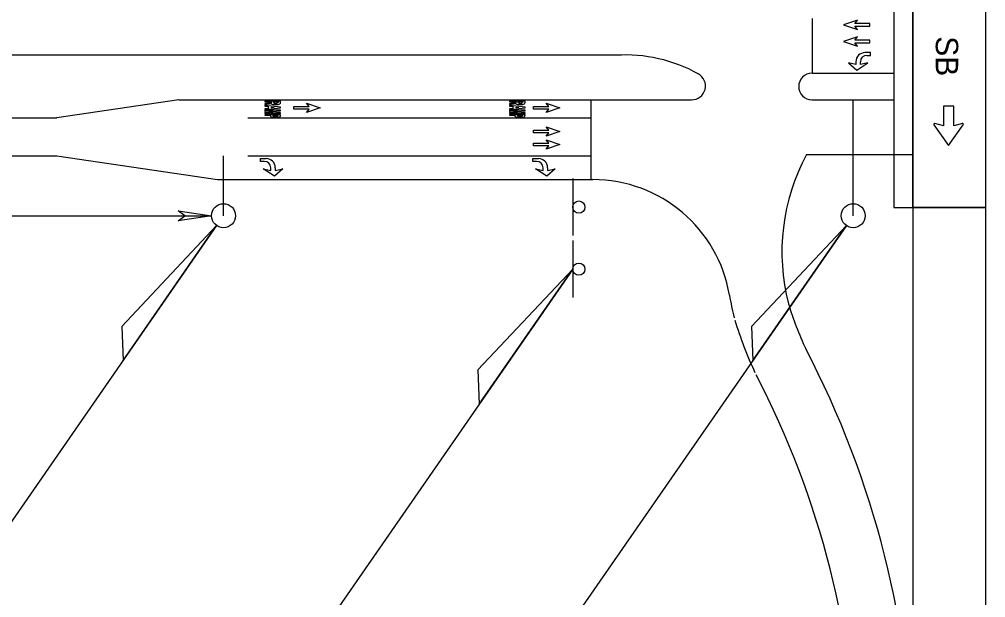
# Model space of a CAD drawing. Extents: x -830008.4 to -829992.7, y 1290284.1 to 1290294.4.
# Drawn here: x -830003.674 to -830000.185, y 1290287.925 to 1290290.014 of the extents above; entities that cross this region are included whole.
import ezdxf

# ---------------------------------------------------------------- set-up
doc = ezdxf.new("R2010")
doc.units = 0
for name, color, linetype in [('DirArrowsPavt', 7, 'Continuous'), ('LeaderLine_dp', 7, 'Continuous'), ('PavtMessage', 7, 'Continuous'), ('SignPanel', 7, 'Continuous'), ('SignSupport', 7, 'Continuous'), ('SignTruss', 7, 'Continuous'), ('TextLabel', 7, 'Continuous')]:
    doc.layers.add(name, color=color, linetype=linetype)

msp = doc.modelspace()

# ---------------------------------------------------------------- linework, layer by layer
at = {"layer": 'DirArrowsPavt'}
for p, q in [((-830000.6481, 1290290.0105), (-830000.6981, 1290289.9938)), ((-830000.6981, 1290289.9938), (-830000.6481, 1290289.9771)), ((-830000.6581, 1290289.9988), (-830000.6481, 1290290.0105)), ((-830000.6031, 1290289.9988), (-830000.6581, 1290289.9988)), ((-830000.6481, 1290289.9771), (-830000.6581, 1290289.9888)), ((-830000.6581, 1290289.9888), (-830000.6031, 1290289.9888)), ((-830000.6031, 1290289.9888), (-830000.6031, 1290289.9988)), ((-830000.6481, 1290289.9498), (-830000.6981, 1290289.9331)), ((-830000.6581, 1290289.9381), (-830000.6481, 1290289.9498)), ((-830000.6981, 1290289.9331), (-830000.6481, 1290289.9165)), ((-830000.6031, 1290289.9381), (-830000.6581, 1290289.9381)), ((-830000.6481, 1290289.9165), (-830000.6581, 1290289.9281)), ((-830000.6581, 1290289.9281), (-830000.6031, 1290289.9281)), ((-830000.6031, 1290289.9281), (-830000.6031, 1290289.9381)), ((-830000.6143, 1290289.8834), (-830000.6006, 1290289.8834)), ((-830002.6279, 1290289.6992), (-830002.6379, 1290289.7108)), ((-830002.6379, 1290289.7108), (-830002.5879, 1290289.6942)), ((-830001.7627, 1290289.6992), (-830001.7727, 1290289.7108)), ((-830001.7727, 1290289.7108), (-830001.7227, 1290289.6942)), ((-830002.6829, 1290289.6892), (-830002.6829, 1290289.6992)), ((-830002.6829, 1290289.6992), (-830002.6279, 1290289.6992)), ((-830002.6279, 1290289.6892), (-830002.6829, 1290289.6892)), ((-830002.5879, 1290289.6942), (-830002.6379, 1290289.6775)), ((-830002.6379, 1290289.6775), (-830002.6279, 1290289.6892)), ((-830001.8177, 1290289.6892), (-830001.8177, 1290289.6992)), ((-830001.8177, 1290289.6992), (-830001.7627, 1290289.6992)), ((-830001.7627, 1290289.6892), (-830001.8177, 1290289.6892)), ((-830001.7227, 1290289.6942), (-830001.7727, 1290289.6775)), ((-830001.7727, 1290289.6775), (-830001.7627, 1290289.6892)), ((-830001.8177, 1290289.6035), (-830001.8177, 1290289.6135)), ((-830001.8177, 1290289.6135), (-830001.7627, 1290289.6135)), ((-830001.7627, 1290289.6035), (-830001.8177, 1290289.6035)), ((-830001.7627, 1290289.6135), (-830001.7727, 1290289.6252)), ((-830001.7727, 1290289.6252), (-830001.7227, 1290289.6085)), ((-830001.7227, 1290289.6085), (-830001.7727, 1290289.5918)), ((-830001.7727, 1290289.5918), (-830001.7627, 1290289.6035)), ((-830001.8177, 1290289.5569), (-830001.8177, 1290289.5669)), ((-830001.8177, 1290289.5669), (-830001.7627, 1290289.5669)), ((-830001.7627, 1290289.5669), (-830001.7727, 1290289.5786)), ((-830001.7727, 1290289.5786), (-830001.7227, 1290289.5619)), ((-830001.7627, 1290289.5569), (-830001.8177, 1290289.5569)), ((-830001.7227, 1290289.5619), (-830001.7727, 1290289.5453)), ((-830001.7727, 1290289.5453), (-830001.7627, 1290289.5569)), ((-830002.7898, 1290289.5005), (-830002.8035, 1290289.5005)), ((-830001.8065, 1290289.5005), (-830001.8202, 1290289.5005))]:
    msp.add_line(p, q, dxfattribs=at)
for points in [[(-830000.6006, 1290289.8834), (-830000.6006, 1290289.8934), (-830000.6211, 1290289.8934)], [(-830000.6539, 1290289.8605), (-830000.6539, 1290289.85), (-830000.6806, 1290289.8567), (-830000.6506, 1290289.83), (-830000.6106, 1290289.8567), (-830000.6373, 1290289.85), (-830000.6373, 1290289.8604)], [(-830002.8035, 1290289.5005), (-830002.8035, 1290289.5105), (-830002.783, 1290289.5105)], [(-830001.8202, 1290289.5005), (-830001.8202, 1290289.5105), (-830001.7997, 1290289.5105)], [(-830002.7502, 1290289.4777), (-830002.7502, 1290289.4672), (-830002.7235, 1290289.4739), (-830002.7535, 1290289.4472), (-830002.7935, 1290289.4739), (-830002.7669, 1290289.4672), (-830002.7669, 1290289.4776)], [(-830001.7668, 1290289.4777), (-830001.7668, 1290289.4672), (-830001.7402, 1290289.4739), (-830001.7702, 1290289.4472), (-830001.8102, 1290289.4739), (-830001.7835, 1290289.4672), (-830001.7835, 1290289.4776)]]:
    msp.add_lwpolyline(points, dxfattribs=at)
for centre, radius, start, end in [((-830000.6211, 1290289.8605), 0.0328, 90, 180), ((-830000.6143, 1290289.8604), 0.023, 90, 180), ((-830002.7898, 1290289.4776), 0.023, 0, 90), ((-830002.783, 1290289.4777), 0.0328, 0, 90), ((-830001.8065, 1290289.4776), 0.023, 0, 90), ((-830001.7997, 1290289.4777), 0.0328, 0, 90)]:
    msp.add_arc(centre, radius, start, end, dxfattribs=at)
at = {"layer": 'LeaderLine_dp'}
for p, q in [((-830003.0766, 1290289.3045), (-830003.1006, 1290289.3225)), ((-830003.1006, 1290289.3225), (-830002.9806, 1290289.3045)), ((-830002.9806, 1290289.3045), (-830003.1006, 1290289.2865)), ((-830003.1006, 1290289.2865), (-830003.0766, 1290289.3045)), ((-830002.962, 1290289.2687), (-830003.3047, 1290288.9047)), ((-830003.3001, 1290288.7811), (-830002.962, 1290289.2687)), ((-830000.6882, 1290289.2687), (-830001.0309, 1290288.9047)), ((-830001.0263, 1290288.7811), (-830000.6882, 1290289.2687)), ((-830001.6762, 1290289.1116), (-830002.0189, 1290288.7475)), ((-830002.0143, 1290288.624), (-830001.6762, 1290289.1116)), ((-830003.3047, 1290288.9047), (-830003.3001, 1290288.7811)), ((-830001.0309, 1290288.9047), (-830001.0263, 1290288.7811)), ((-830002.0189, 1290288.7475), (-830002.0143, 1290288.624))]:
    msp.add_line(p, q, dxfattribs=at)
at = {"layer": 'PavtMessage'}
for p, q in [((-830002.7876, 1290289.7022), (-830002.7876, 1290289.6999)), ((-830002.731, 1290289.6964), (-830002.7876, 1290289.7022)), ((-830002.7876, 1290289.6999), (-830002.7758, 1290289.6982)), ((-830002.7876, 1290289.6881), (-830002.731, 1290289.694)), ((-830002.7758, 1290289.6921), (-830002.7876, 1290289.6905)), ((-830002.7876, 1290289.6905), (-830002.7876, 1290289.6881)), ((-830002.731, 1290289.6854), (-830002.7876, 1290289.6854)), ((-830002.7876, 1290289.6854), (-830002.7876, 1290289.683)), ((-830002.7876, 1290289.683), (-830002.7593, 1290289.683)), ((-830002.7593, 1290289.683), (-830002.7876, 1290289.6807)), ((-830002.7876, 1290289.6807), (-830002.7876, 1290289.6783)), ((-830002.7876, 1290289.6783), (-830002.7593, 1290289.676)), ((-830002.7593, 1290289.676), (-830002.7876, 1290289.676)), ((-830002.7876, 1290289.676), (-830002.7876, 1290289.6736)), ((-830002.7876, 1290289.6736), (-830002.731, 1290289.6736)), ((-830002.7758, 1290289.6982), (-830002.7758, 1290289.6921)), ((-830002.7734, 1290289.6795), (-830002.731, 1290289.683)), ((-830002.731, 1290289.676), (-830002.7734, 1290289.6795)), ((-830002.764, 1290289.6938), (-830002.764, 1290289.6965)), ((-830002.764, 1290289.6965), (-830002.7546, 1290289.6952)), ((-830002.7546, 1290289.6952), (-830002.764, 1290289.6938)), ((-830002.731, 1290289.694), (-830002.731, 1290289.6964)), ((-830002.731, 1290289.683), (-830002.731, 1290289.6854)), ((-830002.731, 1290289.6736), (-830002.731, 1290289.676)), ((-830001.9045, 1290289.7022), (-830001.9045, 1290289.6999)), ((-830001.8478, 1290289.6964), (-830001.9045, 1290289.7022)), ((-830001.9045, 1290289.6999), (-830001.8927, 1290289.6982)), ((-830001.9045, 1290289.6881), (-830001.8478, 1290289.694)), ((-830001.8927, 1290289.6921), (-830001.9045, 1290289.6905)), ((-830001.9045, 1290289.6905), (-830001.9045, 1290289.6881)), ((-830001.8478, 1290289.6854), (-830001.9045, 1290289.6854)), ((-830001.9045, 1290289.6854), (-830001.9045, 1290289.683)), ((-830001.9045, 1290289.683), (-830001.8762, 1290289.683)), ((-830001.8762, 1290289.683), (-830001.9045, 1290289.6807)), ((-830001.9045, 1290289.6807), (-830001.9045, 1290289.6783)), ((-830001.9045, 1290289.6783), (-830001.8762, 1290289.676)), ((-830001.8762, 1290289.676), (-830001.9045, 1290289.676)), ((-830001.9045, 1290289.676), (-830001.9045, 1290289.6736)), ((-830001.9045, 1290289.6736), (-830001.8478, 1290289.6736)), ((-830001.8927, 1290289.6982), (-830001.8927, 1290289.6921)), ((-830001.8903, 1290289.6795), (-830001.8478, 1290289.683)), ((-830001.8478, 1290289.676), (-830001.8903, 1290289.6795)), ((-830001.8809, 1290289.6938), (-830001.8809, 1290289.6965)), ((-830001.8809, 1290289.6965), (-830001.8714, 1290289.6952)), ((-830001.8714, 1290289.6952), (-830001.8809, 1290289.6938)), ((-830001.8478, 1290289.694), (-830001.8478, 1290289.6964)), ((-830001.8478, 1290289.683), (-830001.8478, 1290289.6854)), ((-830001.8478, 1290289.6736), (-830001.8478, 1290289.676)), ((-830002.731, 1290289.6693), (-830002.7876, 1290289.6693)), ((-830002.7876, 1290289.6693), (-830002.7876, 1290289.6669)), ((-830002.7876, 1290289.6669), (-830002.7687, 1290289.6669)), ((-830002.7593, 1290289.6669), (-830002.7404, 1290289.6669)), ((-830002.7569, 1290289.6598), (-830002.7428, 1290289.6598)), ((-830002.7451, 1290289.6622), (-830002.7545, 1290289.6622)), ((-830002.731, 1290289.6669), (-830002.731, 1290289.6693)), ((-830001.8478, 1290289.6693), (-830001.9045, 1290289.6693)), ((-830001.9045, 1290289.6693), (-830001.9045, 1290289.6669)), ((-830001.9045, 1290289.6669), (-830001.8856, 1290289.6669)), ((-830001.8761, 1290289.6669), (-830001.8573, 1290289.6669)), ((-830001.8738, 1290289.6598), (-830001.8596, 1290289.6598)), ((-830001.862, 1290289.6622), (-830001.8714, 1290289.6622)), ((-830001.8478, 1290289.6669), (-830001.8478, 1290289.6693))]:
    msp.add_line(p, q, dxfattribs=at)
for points in [[(-830002.731, 1290289.7146), (-830002.731, 1290289.7178), (-830002.7377, 1290289.7179), (-830002.7603, 1290289.7179), (-830002.7867, 1290289.7179), (-830002.7876, 1290289.7178), (-830002.7876, 1290289.7154), (-830002.7648, 1290289.7154), (-830002.7648, 1290289.7119)], [(-830002.7648, 1290289.7119), (-830002.7876, 1290289.7084), (-830002.7876, 1290289.706), (-830002.7647, 1290289.7092)], [(-830002.7597, 1290289.706), (-830002.7401, 1290289.706)], [(-830002.757, 1290289.7127), (-830002.7569, 1290289.7154), (-830002.7404, 1290289.7154), (-830002.7404, 1290289.7132)], [(-830001.8478, 1290289.7146), (-830001.8478, 1290289.7178), (-830001.8545, 1290289.7179), (-830001.8772, 1290289.7179), (-830001.9036, 1290289.7179), (-830001.9045, 1290289.7178), (-830001.9045, 1290289.7154), (-830001.8817, 1290289.7154), (-830001.8817, 1290289.7119)], [(-830001.8817, 1290289.7119), (-830001.9045, 1290289.7084), (-830001.9045, 1290289.706), (-830001.8816, 1290289.7092)], [(-830001.8766, 1290289.706), (-830001.857, 1290289.706)], [(-830001.8739, 1290289.7127), (-830001.8738, 1290289.7154), (-830001.8573, 1290289.7154), (-830001.8573, 1290289.7132)]]:
    msp.add_lwpolyline(points, dxfattribs=at)
for centre, radius, start, end in [((-830002.7591, 1290289.7126), 0.00659, 210.876, 264.4327), ((-830002.749, 1290289.7223), 0.0125, 229.8768, 313.4926), ((-830002.7404, 1290289.7154), 0.00948, 271.9759, 354.6981), ((-830001.876, 1290289.7126), 0.00659, 210.876, 264.4327), ((-830001.8658, 1290289.7223), 0.0125, 229.8768, 313.4926), ((-830001.8573, 1290289.7154), 0.00948, 271.9759, 354.6981), ((-830002.7545, 1290289.6669), 0.00472, 180, 270), ((-830002.7451, 1290289.6669), 0.00472, 270, 360), ((-830001.8714, 1290289.6669), 0.00472, 180, 270), ((-830001.862, 1290289.6669), 0.00472, 270, 360)]:
    msp.add_arc(centre, radius, start, end, dxfattribs=at)
for centre, start_param, end_param in [((-830002.7569, 1290289.6669), 3.141593, 4.712389), ((-830002.7428, 1290289.6669), 4.71335, 6.283185), ((-830001.8738, 1290289.6669), 3.141593, 4.712389), ((-830001.8596, 1290289.6669), 4.71335, 6.283185)]:
    msp.add_ellipse(centre, major_axis=(0.0118, 0), ratio=0.6, start_param=start_param, end_param=end_param, dxfattribs=at)
at = {"layer": 'SignPanel'}
for p, q in [((-830000.3721, 1290289.6321), (-830000.3721, 1290289.6321)), ((-830000.319, 1290289.5574), (-830000.2659, 1290289.6321))]:
    msp.add_line(p, q, dxfattribs=at)
for points in [[(-830000.2694, 1290289.6379), (-830000.3003, 1290289.6286), (-830000.3003, 1290289.6998), (-830000.3377, 1290289.6998), (-830000.3377, 1290289.6286), (-830000.3686, 1290289.6379)], [(-830000.3721, 1290289.6321), (-830000.319, 1290289.5574), (-830000.319, 1290289.5574)]]:
    msp.add_lwpolyline(points, dxfattribs=at)
for centre, start, end in [((-830000.3692, 1290289.6345), 72.8195, 215.3924), ((-830000.2688, 1290289.6345), 324.6076, 107.1805)]:
    msp.add_arc(centre, 0.00355, start, end, dxfattribs=at)
at = {"layer": 'SignSupport'}
for p, q in [((-830001.6762, 1290289.4386), (-830001.6762, 1290289.2328)), ((-830001.6762, 1290289.2145), (-830001.6762, 1290289.0087))]:
    msp.add_line(p, q, dxfattribs=at)
for centre in [(-830001.6542, 1290289.3357), (-830001.6542, 1290289.1116)]:
    msp.add_circle(centre, 0.0221, dxfattribs=at)
at = {"layer": 'SignTruss'}
for p, q in [((-830000.6635, 1290289.3045), (-830000.6635, 1290289.7229)), ((-830002.9372, 1290289.3045), (-830002.9372, 1290289.5202))]:
    msp.add_line(p, q, dxfattribs=at)
for centre in [(-830002.9372, 1290289.3045), (-830000.6635, 1290289.3045), (-830000.6635, 1290289.3045)]:
    msp.add_circle(centre, 0.0434, dxfattribs=at)
at = {"layer": 'TextLabel'}
for p, q in [((-830000.1852, 1290294.228), (-830000.1852, 1290285.328)), ((-830000.448, 1290293.7828), (-830000.448, 1290288.446)), ((-830000.8113, 1290290.0166), (-830000.8113, 1290289.8188)), ((-830001.5198, 1290289.8838), (-830007.4742, 1290289.8838)), ((-830000.8113, 1290289.8188), (-830000.517, 1290289.8188)), ((-830003.0984, 1290289.7229), (-830003.5393, 1290289.6579)), ((-830003.0984, 1290289.7229), (-830001.247, 1290289.7229)), ((-830001.6094, 1290289.4347), (-830001.6094, 1290289.7229)), ((-830000.8125, 1290289.7229), (-830000.517, 1290289.7229)), ((-830007.4742, 1290289.6579), (-830003.5393, 1290289.6579)), ((-830002.8488, 1290289.6579), (-830001.6094, 1290289.6579)), ((-830007.4742, 1290289.5202), (-830003.5393, 1290289.5202)), ((-830003.5393, 1290289.5202), (-830002.9593, 1290289.4347)), ((-830002.8488, 1290289.5202), (-830001.6094, 1290289.5202)), ((-830000.8318, 1290289.5251), (-830000.448, 1290289.5251)), ((-830002.9593, 1290289.4347), (-830001.6033, 1290289.4347)), ((-830000.448, 1290289.3342), (-830000.1852, 1290289.3342)), ((-830005.2106, 1290289.3045), (-830002.9806, 1290289.3045)), ((-830002.962, 1290289.2687), (-830003.7569, 1290288.1223)), ((-830000.6882, 1290289.2687), (-830001.6523, 1290287.8784)), ((-830001.6762, 1290289.1116), (-830002.665, 1290287.6856)), ((-830000.448, 1290288.446), (-830000.4492, 1290286.7771))]:
    msp.add_line(p, q, dxfattribs=at)
msp.add_lwpolyline([(-830000.448, 1290290.196), (-830000.517, 1290290.196), (-830000.517, 1290289.3342), (-830000.448, 1290289.3342), (-830000.448, 1290290.196)], dxfattribs=at)
msp.add_lwpolyline([(-830000.1852, 1290289.3342), (-830000.448, 1290289.3342), (-830000.448, 1290290.196), (-830000.1852, 1290290.196)], close=True, dxfattribs=at)
for centre, radius, start, end in [((-830001.4861, 1290289.3421), 0.5427, 60.9744, 93.5626), ((-830001.247, 1290289.7729), 0.05, 270, 60.9744), ((-830000.8125, 1290289.7709), 0.0479, 90, 270), ((-830000.1798, 1290289.1727), 0.7411, 151.6081, 194.5356), ((-830001.6033, 1290288.9347), 0.5, 9.4895, 90), ((-830000.1798, 1290289.1727), 0.9433, 189.4895, 194.5356), ((-829999.6893, 1290289.3542), 1.2626, 196.9261, 204.8644), ((-829999.6893, 1290289.3542), 1.4649, 196.9261, 204.8644), ((-830003.8248, 1290287.2554), 3.3762, 0.5435, 27.6732), ((-830003.8248, 1290287.2554), 3.1737, 0.5435, 27.6732)]:
    msp.add_arc(centre, radius, start, end, dxfattribs=at)

# ---------------------------------------------------------------- texts
msp.add_text('SB', height=0.081, rotation=270, dxfattribs=at).set_placement((-830000.3654, 1290289.9525))

doc.saveas('drawing.dxf')
